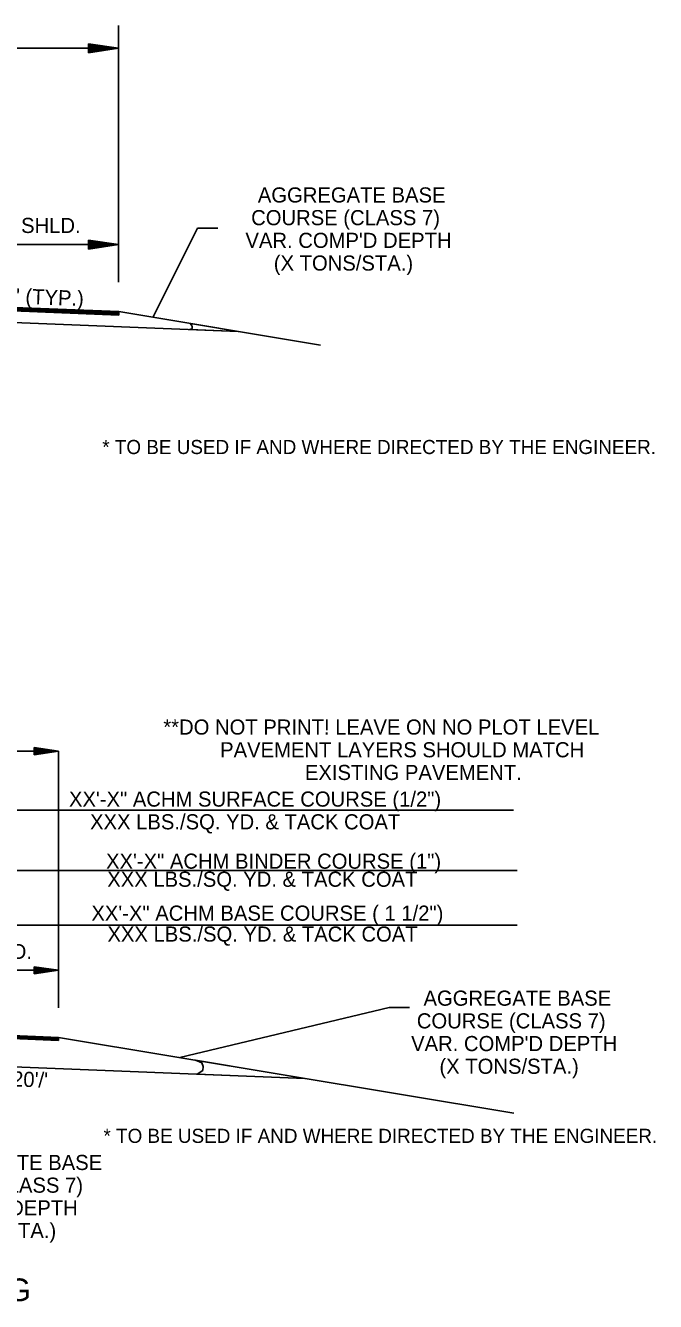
# Model space of a CAD drawing. Extents: x 542112 to 1930787, y -1968972 to 596640.
# Drawn here: x 547104 to 547417, y -1957255 to -1956623 of the extents above; entities that cross this region are included whole.
import ezdxf

# ---------------------------------------------------------------- set-up
doc = ezdxf.new("R2010")
doc.units = 0
for name, color, linetype in [('R_Border Prem', 7, 'Continuous'), ('R_Draft', 7, 'Continuous'), ('R_No Plot', 7, 'Continuous')]:
    doc.layers.add(name, color=color, linetype=linetype)

msp = doc.modelspace()

# ---------------------------------------------------------------- linework, layer by layer
at = {"layer": 'R_Draft'}
for p, q in [((546750.21, -1956633.78), (547150.66, -1956633.78)), ((547135.66, -1956631.53), (547150.66, -1956633.78)), ((547135.66, -1956631.53), (547135.66, -1956636.03)), ((547135.66, -1956631.91), (547148.15, -1956633.78)), ((547135.66, -1956632.29), (547145.57, -1956633.78)), ((547135.66, -1956632.66), (547143.08, -1956633.78)), ((547135.66, -1956633.05), (547140.53, -1956633.78)), ((547135.66, -1956633.43), (547138.03, -1956633.78)), ((547135.66, -1956636.03), (547150.66, -1956633.78)), ((547135.66, -1956634.52), (547140.53, -1956633.78)), ((547135.66, -1956635.27), (547145.57, -1956633.78)), ((547135.66, -1956635.66), (547148.15, -1956633.78)), ((547135.66, -1956634.9), (547143.08, -1956633.78)), ((547135.66, -1956634.13), (547138.03, -1956633.78)), ((547135.66, -1956728.87), (547150.66, -1956731.12)), ((547135.66, -1956728.87), (547135.66, -1956733.37)), ((547135.66, -1956729.24), (547148.15, -1956731.12)), ((547135.66, -1956729.63), (547145.57, -1956731.12)), ((547135.66, -1956730), (547143.08, -1956731.12)), ((547135.66, -1956730.39), (547140.53, -1956731.12)), ((547150.66, -1956731.12), (547070.4, -1956731.12)), ((547135.66, -1956730.77), (547138.03, -1956731.12)), ((547135.66, -1956733.37), (547150.66, -1956731.12)), ((547135.66, -1956731.85), (547140.53, -1956731.12)), ((547135.66, -1956732.61), (547145.57, -1956731.12)), ((547135.66, -1956732.99), (547148.15, -1956731.12)), ((547135.66, -1956732.24), (547143.08, -1956731.12)), ((547135.66, -1956731.47), (547138.03, -1956731.12)), ((547150.73, -1956765.54), (547070.42, -1956762.32)), ((547150.73, -1956765.24), (547070.43, -1956762.02)), ((547150.73, -1956764.93), (547070.45, -1956761.72)), ((547150.73, -1956764.63), (547070.46, -1956761.42)), ((547150.73, -1956764.33), (547070.47, -1956761.12)), ((547209.96, -1956774.2), (547070.33, -1956768.62)), ((547150.73, -1956766.04), (547070.4, -1956762.82)), ((547150.73, -1956765.84), (547070.41, -1956762.62)), ((547150.73, -1956766.03), (547150.73, -1956764.33)), ((547250.8, -1956781.01), (547150.73, -1956764.33)), ((547150.73, -1956764.33), (547150.73, -1956766.03)), ((547150.73, -1956766.04), (547150.73, -1956764.33)), ((547209.96, -1956774.2), (547186.05, -1956773.25)), ((547186.12, -1956770.23), (547190.34, -1956770.93)), ((547190.34, -1956770.93), (547209.96, -1956774.2)), ((546720.38, -1956982.17), (547120.83, -1956982.17)), ((547108.83, -1956980.37), (547120.83, -1956982.17)), ((547108.83, -1956980.37), (547108.83, -1956983.97)), ((547108.83, -1956980.67), (547118.83, -1956982.17)), ((547108.83, -1956980.98), (547116.76, -1956982.17)), ((547108.83, -1956981.28), (547114.76, -1956982.17)), ((547108.83, -1956981.59), (547112.73, -1956982.17)), ((547108.83, -1956981.89), (547110.73, -1956982.17)), ((547108.83, -1956983.97), (547120.83, -1956982.17)), ((547108.83, -1956982.76), (547112.73, -1956982.17)), ((547108.83, -1956983.37), (547116.76, -1956982.17)), ((547108.83, -1956983.67), (547118.83, -1956982.17)), ((547108.83, -1956983.07), (547114.76, -1956982.17)), ((547108.83, -1956982.45), (547110.73, -1956982.17)), ((547346.45, -1957011.41), (547061.54, -1957011.41)), ((547348.37, -1957041.23), (547063.46, -1957041.23)), ((547348.37, -1957068.36), (547065.16, -1957068.36)), ((547120.83, -1957090.77), (547061.54, -1957090.77)), ((547108.83, -1957088.97), (547120.83, -1957090.77)), ((547108.83, -1957088.97), (547108.83, -1957092.57)), ((547108.83, -1957089.27), (547118.83, -1957090.77)), ((547108.83, -1957089.58), (547116.76, -1957090.77)), ((547108.83, -1957089.88), (547114.76, -1957090.77)), ((547108.83, -1957090.19), (547112.73, -1957090.77)), ((547108.83, -1957090.49), (547110.73, -1957090.77)), ((547108.83, -1957092.57), (547120.83, -1957090.77)), ((547108.83, -1957091.36), (547112.73, -1957090.77)), ((547108.83, -1957091.96), (547116.76, -1957090.77)), ((547108.83, -1957092.27), (547118.83, -1957090.77)), ((547108.83, -1957091.66), (547114.76, -1957090.77)), ((547108.83, -1957091.05), (547110.73, -1957090.77)), ((547120.9, -1957125.49), (547040.58, -1957122.27)), ((547120.9, -1957125.19), (547040.59, -1957121.97)), ((547120.9, -1957124.89), (547040.61, -1957121.67)), ((547120.9, -1957124.59), (547040.62, -1957121.37)), ((547120.9, -1957124.29), (547040.63, -1957121.07)), ((547120.9, -1957123.99), (547040.64, -1957120.78)), ((547346.7, -1957161.62), (547120.9, -1957123.99)), ((547120.9, -1957125.49), (547120.9, -1957123.99)), ((547188.73, -1957135.29), (547223.37, -1957141.06)), ((547242.98, -1957144.33), (547040.51, -1957136.23)), ((547223.37, -1957141.06), (547242.98, -1957144.33)), ((547242.98, -1957144.33), (547214.11, -1957143.18))]:
    msp.add_line(p, q, dxfattribs=at)
for points in [[(547150.66, -1956622.52), (547150.66, -1956749.78)], [(547199.85, -1956723.03), (547189.85, -1956723.03), (547167.66, -1956767.16)], [(547186.05, -1956773.25), (547186.94, -1956772.92), (547187.18, -1956772.45), (547187.22, -1956771.75), (547186.83, -1956771.02), (547186.12, -1956770.23)], [(547120.83, -1956982.17), (547120.83, -1957109.43)], [(547294.87, -1957109.16), (547284.87, -1957109.16), (547180.98, -1957134)], [(547214.11, -1957143.18), (547189.66, -1957142.2), (547192.48, -1957140.41), (547192.54, -1957138.37), (547191.91, -1957136.61), (547188.73, -1957135.29)]]:
    msp.add_lwpolyline(points, dxfattribs=at)

# ---------------------------------------------------------------- texts
at = {"layer": 'R_Border Prem'}
msp.add_text('* TO BE USED IF AND WHERE DIRECTED BY THE ENGINEER.', height=7, dxfattribs=at).set_placement((547142.55, -1956834.91))
at = {"layer": 'R_Draft'}
for s, height, p in [('AGGREGATE BASE', 7.5, (547219.71, -1956710.24)), ('X\'-0" SHLD.', 7.5, (547078.43, -1956725.35)), ('COURSE (CLASS 7)', 7.5, (547216.4, -1956721.49)), ("VAR. COMP'D DEPTH", 7.5, (547213.57, -1956732.74)), ('(X TONS/STA.)', 7.5, (547227.62, -1956743.99)), ('XX\'-X" ACHM SURFACE COURSE (1/2") ', 7.5, (547126.05, -1957009.65)), ('XXX LBS./SQ. YD. & TACK COAT', 7.5, (547136.51, -1957020.91)), ('XX\'-X" ACHM BINDER COURSE (1") ', 7.5, (547144.44, -1957040.42)), ('XXX LBS./SQ. YD. & TACK COAT', 7.5, (547145.03, -1957049.36)), ('XX\'-X" ACHM BASE COURSE ( 1 1/2") ', 7.5, (547137.17, -1957066.17)), ('XXX LBS./SQ. YD. & TACK COAT', 7.5, (547145.14, -1957076.54)), ('X\'-0" SHLD.', 7.5, (547054.3, -1957085.18)), ('AGGREGATE BASE', 7.5, (547301.87, -1957108.31)), ('COURSE (CLASS 7)', 7.5, (547298.56, -1957119.56)), ("VAR. COMP'D DEPTH", 7.5, (547295.73, -1957130.81)), ('(X TONS/STA.)', 7.5, (547309.78, -1957142.06)), ('* TO BE USED IF AND WHERE DIRECTED BY THE ENGINEER.', 7, (547143.16, -1957176.3)), ('X\'-X" AGGREGATE BASE', 7.5, (547024.46, -1957189.74)), ('COURSE (CLASS 7)', 7.5, (547039.4, -1957200.99)), ('X" COMP\'D DEPTH', 7.5, (547041.35, -1957212.24)), ('(X TONS/STA.)', 7.5, (547050.62, -1957223.49)), ('2 LANE OPEN SHOULDER OVERLAY WITH MINOR WIDENING', 11.25, (546667.49, -1957254.73))]:
    msp.add_text(s, height=height, dxfattribs=at).set_placement(p)
for s, p in [("0.040'/' (TYP.) ", (547069.86, -1956759.17)), ("0.020'/' ", (547083.79, -1957147.72))]:
    msp.add_text(s, height=7.5, rotation=357.81683, dxfattribs=at).set_placement(p)
at = {"layer": 'R_No Plot'}
for s, p in [('**DO NOT PRINT! LEAVE ON NO PLOT LEVEL', (547172.84, -1956973.95)), ('PAVEMENT LAYERS SHOULD MATCH ', (547201.01, -1956985.2)), ('EXISTING PAVEMENT.', (547243.05, -1956996.45))]:
    msp.add_text(s, height=7.5, dxfattribs=at).set_placement(p)

doc.saveas('drawing.dxf')
